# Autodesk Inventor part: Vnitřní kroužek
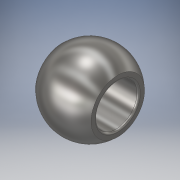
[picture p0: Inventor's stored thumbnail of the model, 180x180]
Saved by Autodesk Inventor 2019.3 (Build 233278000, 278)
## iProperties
Created: 2019-01
Part Number: Vnitřní kroužek
Material: Ocel, legovaná
Document SubType Name: Modeling
Designer: B-hon
Density: 7.73 g/cm^3
Appearance: Pololeštěná
Author: B-hon
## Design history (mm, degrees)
sketch "Náčrt1"
  geometry: L1 (0, 0)-(9.345, 0); L2 (-7.5, 6)-(7.5, 6); L3 (8, 6.5)-(8, 7.695); L4 (-8, 6.5)-(-8, 7.695); A1 r 11.1 centre (0, 0) between (8, 7.695) and (-8, 7.695); A2 r 0.5 centre (-7.5, 6.5) between (-8, 6.5) and (-7.5, 6); A3 r 0.5 centre (7.5, 6.5) between (7.5, 6) and (8, 6.5); 3 further points
  constraints: 8 end point, 6 point on circle, 5 point on line, 4 tangent, 3 centre point, 2 horizontal, 2 perpendicular, 1 coincident, 1 equal radius, 1 horizontal alignment, 1 vertical alignment
  dimensions: "d0" = 11.1 radius of A1; "d1" = 16 distance of point (-8, 6) point (8, 6); "d2" = 12 diameter of L2 L1; "d3" = 0.5 radius of A2
revolve "Rotace1" sketch "Náčrt1" stored, may be unused: angle "d4" = 90 deg
node "Těleso1"
